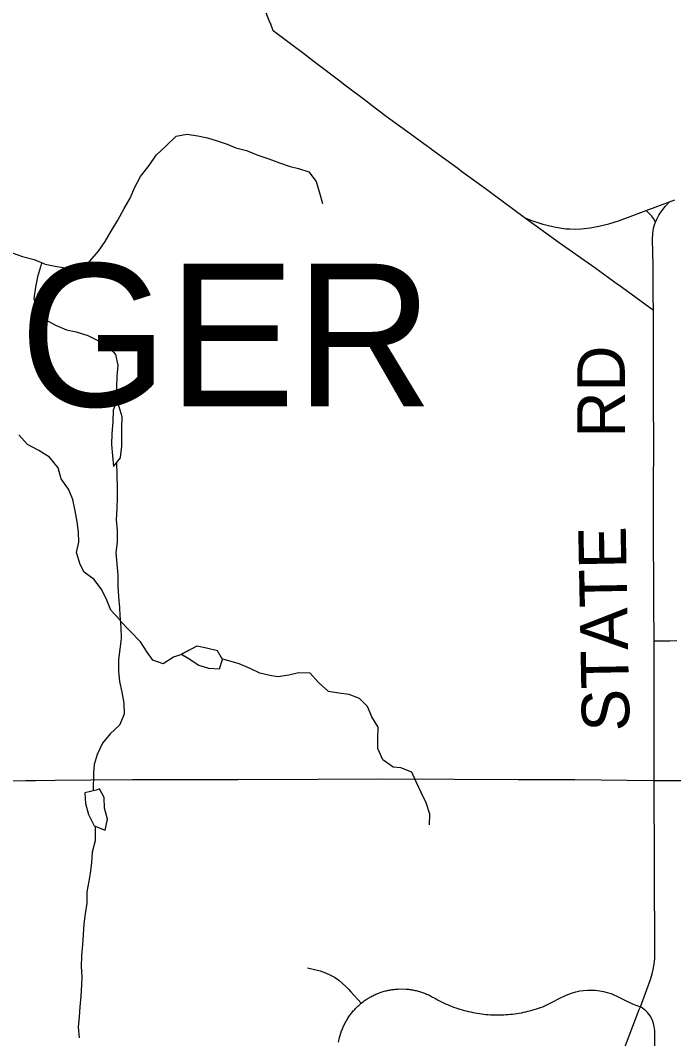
# Model space of a CAD drawing. Extents: x 0 to 34, y 0 to 22.
# Drawn here: x 6.193 to 6.974, y 15.589 to 16.805 of the extents above; entities that cross this region are included whole.
import ezdxf

# ---------------------------------------------------------------- set-up
doc = ezdxf.new("R2010")
doc.units = 0
for name, color, linetype in [('GM_X_County_Road', 7, 'Continuous'), ('GM_X_County_Road_Text', 7, 'Continuous'), ('GM_X_Minor_Lake', 7, 'Continuous'), ('GM_X_Minor_River', 7, 'Continuous'), ('GM_X_Township_Road', 7, 'Continuous'), ('GM_X_Township_Text', 7, 'Continuous')]:
    doc.layers.add(name, color=color, linetype=linetype)

msp = doc.modelspace()

# ---------------------------------------------------------------- linework, layer by layer
at = {"layer": 'GM_X_County_Road'}
for points in [[(6.9505, 15.8976), (6.9504, 16.0528), (6.9504, 16.0643), (6.9501, 16.1088), (6.9499, 16.1376), (6.9496, 16.1807), (6.9495, 16.2148), (6.9496, 16.2435), (6.9498, 16.3021), (6.9495, 16.3497), (6.9496, 16.4286), (6.9494, 16.4587), (6.9081, 16.489), (6.9079, 16.4891), (6.8795, 16.5099), (6.8367, 16.5395), (6.7949, 16.57), (6.7566, 16.5984), (6.7515, 16.6023), (6.7204, 16.625), (6.7159, 16.6283), (6.6845, 16.6513), (6.682, 16.6531), (6.6797, 16.6548), (6.6502, 16.6763), (6.6464, 16.6791), (6.6304, 16.6907), (6.6121, 16.7046), (6.6076, 16.708), (6.5795, 16.7292), (6.5749, 16.7327), (6.546, 16.7546), (6.5444, 16.7558), (6.5314, 16.7656), (6.5175, 16.776), (6.4955, 16.7927), (6.492, 16.8019), (6.4919, 16.8022), (6.4736, 16.8498)], [(6.1725, 15.8971), (6.2, 15.8976), (6.2117, 15.8977), (6.2352, 15.8979), (6.2775, 15.8982), (6.3275, 15.8986), (6.3417, 15.8987), (6.3656, 15.8988), (6.3978, 15.8989), (6.4238, 15.8988), (6.453, 15.8989), (6.549, 15.8993), (6.6246, 15.8995), (6.7118, 15.8993), (6.7879, 15.8988), (6.8557, 15.8986), (6.9495, 15.8976)], [(6.9495, 15.8976), (6.9505, 15.8976), (7.0073, 15.8977)]]:
    msp.add_lwpolyline(points, dxfattribs=at)
at = {"layer": 'GM_X_Minor_Lake'}
for points in [[(6.3092, 16.3518), (6.3042, 16.3398), (6.3038, 16.3257), (6.3027, 16.312), (6.3023, 16.2987), (6.3035, 16.2854), (6.3046, 16.2725), (6.313, 16.2828), (6.3135, 16.2874)], [(6.3135, 16.2874), (6.3145, 16.2965), (6.3145, 16.3094), (6.3148, 16.3189), (6.3152, 16.3318), (6.3092, 16.3518)], [(6.3135, 16.2874), (6.3145, 16.2965), (6.3145, 16.3094), (6.3148, 16.3189), (6.3152, 16.3318), (6.3092, 16.3517)], [(6.435, 16.0419), (6.4288, 16.0525), (6.4159, 16.0554), (6.4044, 16.058), (6.3855, 16.0482)], [(6.435, 16.0419), (6.4288, 16.0525), (6.4159, 16.0554), (6.4044, 16.058), (6.3858, 16.0484)], [(6.3858, 16.0484), (6.3939, 16.0435), (6.4065, 16.0352), (6.4183, 16.0315), (6.4312, 16.0308), (6.435, 16.0419)], [(6.386, 16.0482), (6.3939, 16.0435), (6.4065, 16.0352), (6.4183, 16.0315), (6.4312, 16.0308), (6.435, 16.0419)], [(6.284, 15.8861), (6.2706, 15.883), (6.2714, 15.8701), (6.2748, 15.8568), (6.2817, 15.8435), (6.2946, 15.8382), (6.2976, 15.8515), (6.2951, 15.8601)], [(6.2839, 15.8861), (6.2706, 15.883), (6.2714, 15.8701), (6.2748, 15.8568), (6.2817, 15.8435), (6.2946, 15.8382), (6.2976, 15.8515), (6.2951, 15.8601)], [(6.2951, 15.8601), (6.2938, 15.8644), (6.2934, 15.8773), (6.2881, 15.8876), (6.2839, 15.8861)], [(6.2951, 15.8601), (6.2938, 15.8644), (6.2934, 15.8773), (6.2881, 15.8876), (6.284, 15.8861)]]:
    msp.add_lwpolyline(points, dxfattribs=at)
at = {"layer": 'GM_X_Minor_River'}
for points in [[(6.1825, 16.5283), (6.1962, 16.5234), (6.2099, 16.5196), (6.2232, 16.5143), (6.2369, 16.5116), (6.2506, 16.5093), (6.2643, 16.5105), (6.2765, 16.5177), (6.2868, 16.5299), (6.2947, 16.5413), (6.3019, 16.5535), (6.3099, 16.5668), (6.3175, 16.5805), (6.3247, 16.5931), (6.33, 16.606), (6.3369, 16.619), (6.3471, 16.6319), (6.3555, 16.6445), (6.368, 16.6559), (6.3794, 16.6669), (6.3923, 16.6696), (6.4053, 16.6674), (6.4171, 16.6651), (6.4285, 16.6613), (6.4403, 16.6575), (6.4509, 16.6533), (6.4635, 16.6499), (6.4772, 16.6442), (6.4902, 16.6401), (6.5031, 16.6351), (6.5157, 16.631), (6.5256, 16.6283), (6.5381, 16.6245), (6.5469, 16.6128), (6.5507, 16.5995), (6.5542, 16.5865)], [(6.2187, 16.5158), (6.2175, 16.5112), (6.2141, 16.499), (6.2115, 16.4869), (6.2096, 16.4732), (6.213, 16.4595), (6.2233, 16.4481), (6.2355, 16.4413), (6.2485, 16.4359), (6.2603, 16.4333), (6.274, 16.4291), (6.2858, 16.4231), (6.2976, 16.4174), (6.3071, 16.4064), (6.3098, 16.3934), (6.3087, 16.3805), (6.3083, 16.3668), (6.3092, 16.3517)], [(6.3123, 16.0893), (6.3129, 16.0888), (6.3015, 16.101), (6.2969, 16.1131), (6.2908, 16.1253), (6.2816, 16.1375), (6.2698, 16.1462), (6.2649, 16.1557), (6.2606, 16.1698), (6.2633, 16.1823), (6.2629, 16.1941), (6.2614, 16.2066), (6.2591, 16.2196), (6.256, 16.2333), (6.251, 16.2454), (6.2423, 16.258), (6.2388, 16.2709), (6.2281, 16.2838), (6.2156, 16.2918), (6.2019, 16.299), (6.1916, 16.3104)], [(6.3084, 16.2772), (6.3089, 16.2466), (6.3089, 16.2352), (6.3085, 16.2223), (6.3078, 16.209), (6.3089, 16.1961), (6.309, 16.1824), (6.3075, 16.1694), (6.3086, 16.1565), (6.3098, 16.1428), (6.3098, 16.1299), (6.3106, 16.117), (6.3117, 16.104), (6.3121, 16.0945), (6.3133, 16.0808), (6.3137, 16.0671), (6.3122, 16.0542), (6.3107, 16.042), (6.3107, 16.0283), (6.3119, 16.0158), (6.3145, 16.0032), (6.3172, 15.9899), (6.3176, 15.9766), (6.3119, 15.9637), (6.3009, 15.9534), (6.2914, 15.942), (6.285, 15.9287), (6.2816, 15.9165), (6.2808, 15.9066), (6.2806, 15.8853)], [(6.386, 16.0482), (6.3765, 16.0448), (6.364, 16.0368), (6.3518, 16.0413), (6.3449, 16.0508), (6.3369, 16.063), (6.3123, 16.0887)], [(6.6819, 15.8444), (6.6823, 15.8573), (6.6781, 15.871), (6.672, 15.8831), (6.6663, 15.8961), (6.6609, 15.9075), (6.648, 15.9128), (6.6385, 15.9135), (6.6263, 15.9222), (6.6205, 15.9356), (6.6202, 15.9477), (6.6209, 15.9614), (6.6133, 15.9736), (6.6079, 15.9861), (6.5984, 15.9956), (6.5862, 16.0002), (6.5737, 16.002), (6.5615, 16.0039), (6.5493, 16.0146), (6.5394, 16.0256), (6.5257, 16.0263), (6.5139, 16.0233), (6.501, 16.0214), (6.4914, 16.0229), (6.4796, 16.0259), (6.4678, 16.0312), (6.4549, 16.0369), (6.434, 16.0429)], [(6.2829, 15.8425), (6.2828, 15.8256), (6.2794, 15.8119), (6.2783, 15.7994), (6.2768, 15.7868), (6.2753, 15.7773), (6.2727, 15.7647), (6.2727, 15.7511), (6.2708, 15.7385), (6.2693, 15.7263), (6.2685, 15.7138), (6.2678, 15.7016), (6.2663, 15.6883), (6.2659, 15.6754), (6.2667, 15.6632), (6.2663, 15.6537), (6.2656, 15.64), (6.2645, 15.6274), (6.2637, 15.6153), (6.2626, 15.6031), (6.2638, 15.5902)]]:
    msp.add_lwpolyline(points, dxfattribs=at)
at = {"layer": 'GM_X_Township_Road'}
for points in [[(6.7949, 16.57), (6.8052, 16.5659), (6.8124, 16.5634), (6.8173, 16.5618), (6.8227, 16.5606), (6.8311, 16.5588), (6.8401, 16.5572), (6.8449, 16.5565), (6.8495, 16.5562), (6.8561, 16.5561), (6.8632, 16.5563), (6.8737, 16.5574), (6.8842, 16.5595), (6.8962, 16.5625), (6.9091, 16.5664), (6.9408, 16.5783), (6.9685, 16.5887), (6.9748, 16.5909)], [(6.9494, 16.4587), (6.9492, 16.4768), (6.949, 16.5119), (6.9484, 16.5442), (6.9488, 16.5509), (6.9495, 16.557), (6.9506, 16.5612), (6.952, 16.5645), (6.9535, 16.5679), (6.9559, 16.5728), (6.9593, 16.5779), (6.9635, 16.583), (6.9685, 16.5887)], [(6.952, 16.5645), (6.9494, 16.5687), (6.947, 16.5718), (6.9439, 16.575), (6.9408, 16.5783)], [(6.9504, 16.0643), (6.9689, 16.0645), (6.9775, 16.0647)], [(6.774, 15.2302), (6.7766, 15.2367), (6.7977, 15.2874), (6.8113, 15.3196), (6.8525, 15.4198), (6.8554, 15.4267), (6.8647, 15.4493), (6.8657, 15.4517), (6.8781, 15.4825), (6.8843, 15.498), (6.8845, 15.4983), (6.9326, 15.6239), (6.9339, 15.6272), (6.946, 15.66), (6.9481, 15.6667), (6.9493, 15.672), (6.9504, 15.6782), (6.951, 15.6849), (6.9511, 15.6899), (6.9505, 15.8976)], [(6.5365, 15.6737), (6.5515, 15.6701), (6.5579, 15.668), (6.564, 15.6652), (6.5685, 15.6625), (6.5736, 15.6592), (6.582, 15.6515), (6.5854, 15.6483), (6.5883, 15.6453), (6.6005, 15.6315)], [(6.5734, 15.5849), (6.5745, 15.5906), (6.5762, 15.5958), (6.5771, 15.5984), (6.5776, 15.5996), (6.5781, 15.6008), (6.5786, 15.6021), (6.5791, 15.6033), (6.5796, 15.6045), (6.5802, 15.6057), (6.5808, 15.6069), (6.5814, 15.6081), (6.582, 15.6092), (6.5826, 15.6104), (6.5833, 15.6115), (6.584, 15.6127), (6.5847, 15.6138), (6.5854, 15.6149), (6.5862, 15.616), (6.5869, 15.6171), (6.5877, 15.6181), (6.5885, 15.6192), (6.5893, 15.6202), (6.5902, 15.6213), (6.591, 15.6223), (6.5919, 15.6233), (6.5928, 15.6242), (6.5937, 15.6252), (6.5946, 15.6262), (6.5956, 15.6271), (6.5965, 15.628), (6.5975, 15.6289), (6.5985, 15.6298), (6.5995, 15.6307), (6.6005, 15.6315), (6.6021, 15.6328), (6.6032, 15.6336), (6.6042, 15.6344), (6.6053, 15.6351), (6.6064, 15.6359), (6.6075, 15.6366), (6.6086, 15.6373), (6.6098, 15.638), (6.6109, 15.6387), (6.6121, 15.6393), (6.6133, 15.6399), (6.6144, 15.6405), (6.6156, 15.6411), (6.6168, 15.6417), (6.618, 15.6422), (6.6193, 15.6428), (6.6205, 15.6433), (6.6217, 15.6437), (6.623, 15.6442), (6.6242, 15.6446), (6.6255, 15.645), (6.6267, 15.6454), (6.628, 15.6458), (6.6293, 15.6462), (6.6306, 15.6465), (6.6319, 15.6468), (6.6332, 15.6471), (6.6345, 15.6473), (6.6358, 15.6476), (6.6371, 15.6478), (6.6384, 15.648), (6.6397, 15.6481), (6.641, 15.6483), (6.6424, 15.6484), (6.6437, 15.6485), (6.645, 15.6486), (6.6543, 15.6484), (6.6556, 15.6483), (6.6569, 15.6482), (6.6582, 15.648), (6.6596, 15.6478), (6.6609, 15.6476), (6.6622, 15.6474), (6.6635, 15.6472), (6.6648, 15.6469), (6.6661, 15.6466), (6.6674, 15.6463), (6.6686, 15.646), (6.6699, 15.6456), (6.6712, 15.6452), (6.6725, 15.6448), (6.6737, 15.6444), (6.675, 15.6439), (6.6762, 15.6435), (6.6774, 15.643), (6.6786, 15.6425), (6.6799, 15.6419), (6.6811, 15.6414), (6.6823, 15.6408), (6.6834, 15.6402), (6.6846, 15.6396), (6.6858, 15.6389), (6.6869, 15.6383), (6.6892, 15.637), (6.6915, 15.6357), (6.6939, 15.6345), (6.6963, 15.6333), (6.6986, 15.6321), (6.701, 15.631), (6.7035, 15.6299), (6.7059, 15.6289), (6.7084, 15.6279), (6.7108, 15.627), (6.7133, 15.6261), (6.7158, 15.6253), (6.7184, 15.6244), (6.7209, 15.6237), (6.7235, 15.623), (6.726, 15.6223), (6.7286, 15.6216), (6.7312, 15.6211), (6.7338, 15.6205), (6.7364, 15.62), (6.739, 15.6196), (6.7416, 15.6192), (6.7442, 15.6188), (6.7469, 15.6185), (6.7495, 15.6182), (6.7521, 15.618), (6.7548, 15.6178), (6.7574, 15.6177), (6.7601, 15.6176), (6.7707, 15.6177), (6.7733, 15.6179), (6.776, 15.6181), (6.7786, 15.6183), (6.7812, 15.6186), (6.7839, 15.6189), (6.7865, 15.6193), (6.7891, 15.6198), (6.7917, 15.6202), (6.7943, 15.6207), (6.7969, 15.6213), (6.7995, 15.6219), (6.802, 15.6225), (6.8046, 15.6232), (6.8071, 15.624), (6.8097, 15.6248), (6.8122, 15.6256), (6.8147, 15.6265), (6.8172, 15.6274), (6.8196, 15.6284), (6.8293, 15.6333), (6.837, 15.6372), (6.8453, 15.6412), (6.8515, 15.6437), (6.8569, 15.6453), (6.8614, 15.6462), (6.8661, 15.6468), (6.8707, 15.6471), (6.8799, 15.647), (6.8855, 15.6464), (6.8899, 15.6457), (6.8941, 15.6445), (6.899, 15.643), (6.909, 15.6385), (6.9176, 15.6341), (6.9252, 15.6306), (6.9339, 15.6272)], [(6.9497, 15.6075), (6.9482, 15.6114), (6.9456, 15.6165), (6.9425, 15.6203), (6.9403, 15.6225), (6.9365, 15.6256), (6.9339, 15.6272)], [(6.9523, 15.3566), (6.952, 15.4023), (6.9517, 15.4498), (6.9517, 15.5502), (6.951, 15.5991), (6.9505, 15.6039), (6.9497, 15.6075)]]:
    msp.add_lwpolyline(points, dxfattribs=at)

# ---------------------------------------------------------------- texts
at = {"layer": 'GM_X_County_Road_Text'}
for s, rotation, p in [('RD', 90, (6.9153, 16.3072)), ('STATE', 91.106, (6.9211, 15.9566))]:
    msp.add_text(s, height=0.05682, rotation=rotation, dxfattribs=at).set_placement(p)
at = {"layer": 'GM_X_Township_Text'}
msp.add_text('GRANGER', height=0.17045, rotation=0, dxfattribs=at).set_placement((5.5339, 16.3443))

doc.saveas('drawing.dxf')
